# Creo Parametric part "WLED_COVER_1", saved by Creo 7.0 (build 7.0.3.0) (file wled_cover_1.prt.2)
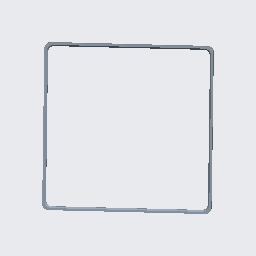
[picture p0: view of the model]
Units: millimeter Kilogram Sec (mmKs); MM, KILOGRAM, SECS

Created from: XX_SOLID_PART_MMKS_ABS.PRT

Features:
  1. coordinate system
  2. datum plane "RIGHT"
  3. datum plane "TOP"
  4. datum plane "FRONT"
  5. extrusion "Extrude 1"
  6. round "Round 1"
  7. chamfer "Chamfer 1"

Surfaces: 18 plane, 8 cylinder, 8 cone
